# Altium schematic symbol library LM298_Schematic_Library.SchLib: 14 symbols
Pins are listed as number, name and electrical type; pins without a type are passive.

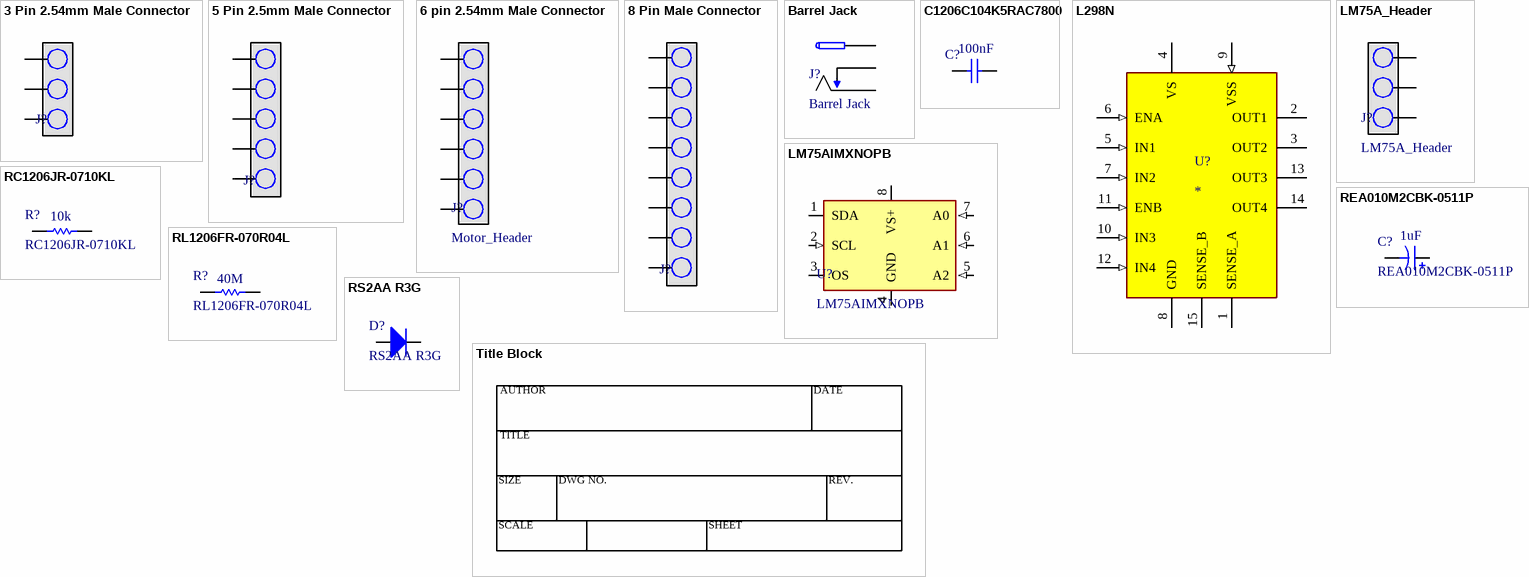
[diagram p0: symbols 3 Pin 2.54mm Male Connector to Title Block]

## 3 Pin 2.54mm Male Connector
designator J?  (value not drawn)
footprint 3 Pin THT Header (Pin Header, pitch 2.54 mm, THT, Vertical, single row, 3p)
pins: 1, 2, 3

## 5 Pin 2.5mm Male Connector
designator J?  (value not drawn)
pins: 1, 2, 3, 4, 5

## 6 pin 2.54mm Male Connector
designator J?, comment Motor_Header
footprint 6 Pin THT Header (Pin Header, pitch 2.54 mm, THT, Vertical, single row, 6p)
pins: 1, 2, 3, 4, 5, 6

## 8 Pin Male Connector
designator J?
footprint 8 Pin THT Header (Pin Header, pitch 2.54 mm, THT, Vertical, single row, 8p)
pins: 1, 2, 3, 4, 5, 6, 7, 8

## Barrel Jack
designator J?
footprint GRAVITECH_CON-SOCJ-2155
pins: 1 POS, 2 NEG, 3 SW

## C1206C104K5RAC7800
designator C?  Capacitance: 100nF  (hidden comment: C1206C104K5RAC7800)
0.1 µF ±10% 50V Ceramic Capacitor X7R 1206 (3216 Metric)
footprint CAP_1206
pins: 1, 2

## L298N
designator U?
Dual Full Bridge Motor Driver 15-Pin(15+Tab) MULTIWATT V Tube; MP: L298N
footprint L298N
pins: 1 SENSE_A, 2 OUT1, 3 OUT2, 4 VS (power), 5 IN1 (in), 6 ENA (in), 7 IN2 (in), 8 GND (power), 9 VSS (in), 10 IN3 (in), 11 ENB (in), 12 IN4 (in), 13 OUT3 (oc), 14 OUT4, 15 SENSE_B

## LM75A_Header
designator J?
2.54mm Male Header Pins
pins: 1, 2, 3

## LM75AIMXNOPB
designator U?
No Description Available; Mfr_Name: Texas Instruments
footprint SOIC8
pins: 1 SDA (io), 2 SCL (in), 3 OS, 4 GND (power), 5 A2 (in), 6 A1 (in), 7 A0 (in), 8 VS+ (power)

## RC1206JR-0710KL
designator R?  value 10k
Res Thick Film 1206 10K Ohm 5% 1/4W ¦100ppm/¦C SMD Paper T/R; Manufacturer: Yageo; Temperature Coefficient: 100ppm/°C; Power Rating: 250mW; Voltage Rating: 200V
footprint RES_1206
pins: 1, 2

## REA010M2CBK-0511P
designator C?  value 1uF
Radial Leaded 160V 1.0uF 20% 5x11mm; Manufacturer: Lelon; Dielectric Material: Aluminium; Polarity: Polarized; Ripple Current: 20mA
footprint CAP_TH_Radial_0511
pins: 1 -, 2 +

## RL1206FR-070R04L
designator R?  value 40M
SMD Current Sense Resistor, 40 Milliohms, ± 1%, 250 mW, 1206 [3216 Metric], Thick Film; Manufacturer: Yageo; Power Rating: 250mW; Temperature Coefficient: 1200ppm/°C
footprint RES_1206
pins: 1, 2

## RS2AA R3G
designator D?
Diode Fast Recovery Rectifier 50V 1.5A 2-Pin DO-214AC Plastic T/R; Manufacturer: Taiwan Semiconductor
footprint RS2AA
pins: 1 K, 2 A

## Title Block
designator *  (value not drawn)  (graphical)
